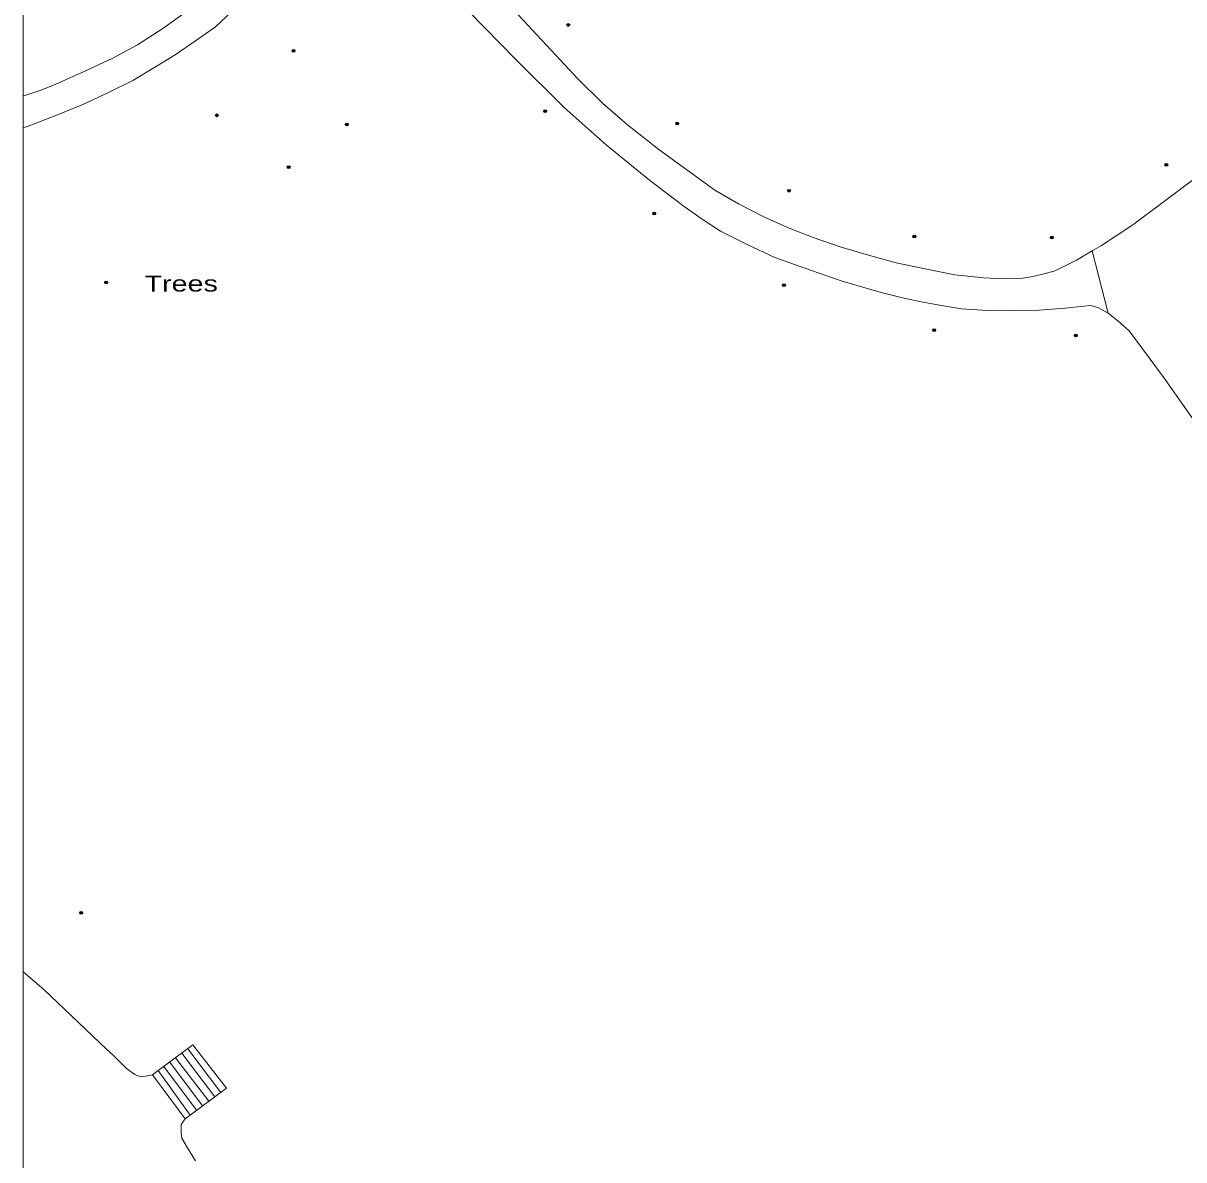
# Model space of a CAD drawing. Extents: x 528790 to 529292, y 179350 to 179856.
# Drawn here: x 528790.2 to 528918, y 179559 to 179684.2 of the extents above; entities that cross this region are included whole.
import ezdxf

# ---------------------------------------------------------------- set-up
doc = ezdxf.new("R2010")
doc.units = 0
doc.header["$LTSCALE"] = 0.6
doc.header["$PDMODE"] = 32
doc.header["$PDSIZE"] = 0.3
for name, color, linetype, lineweight in [('1', 7, 'Continuous', 13), ('2', 7, 'Continuous', 13), ('7', 7, 'Continuous', 13)]:
    doc.layers.add(name, color=color, linetype=linetype, lineweight=lineweight)
doc.layers.add('3', color=7, linetype='Continuous')
doc.layers.add('5', color=7, linetype='Continuous')

msp = doc.modelspace()

# ---------------------------------------------------------------- linework, layer by layer
at = {"layer": '1'}
for points in [[(528790.22, 179728.634), (528790.22, 179676.205), (528790.4, 179676.25), (528792.1, 179676.8), (528793.8, 179677.5), (528797, 179678.9), (528800, 179680.3), (528802.8, 179681.8), (528805.6, 179683.6), (528810, 179686.8)], [(528892.8, 179656.5), (528889.55, 179657.15), (528886.35, 179657.8), (528883.3, 179658.65), (528880.2, 179659.55), (528877.2, 179660.6), (528874.4, 179661.7), (528871.7, 179662.9), (528869, 179664.3), (528866.4, 179665.8), (528860.2, 179670.3), (528856.75, 179673), (528854, 179675.4), (528851.35, 179678.05), (528846.8, 179682.9), (528841.8, 179688.3)], [(528841.8, 179688.3), (528846.8, 179682.9), (528851.35, 179678.05), (528854, 179675.4), (528856.75, 179673), (528860.2, 179670.3), (528866.4, 179665.8), (528869, 179664.3), (528871.7, 179662.9), (528874.4, 179661.7), (528877.2, 179660.6), (528880.2, 179659.55), (528883.3, 179658.65), (528886.35, 179657.8), (528889.55, 179657.15), (528892.8, 179656.5), (528896, 179656.15), (528898.15, 179656.05), (528900.3, 179656.1), (528901.4, 179656.3), (528902.6, 179656.6), (528903.75, 179656.9), (528904.8, 179657.4), (528906.2, 179658.1), (528907.93, 179659.11)], [(528810, 179686.8), (528805.6, 179683.6), (528802.8, 179681.8), (528800, 179680.3), (528797, 179678.9), (528793.8, 179677.5), (528792.1, 179676.8), (528790.4, 179676.25), (528790.22, 179676.205), (528790.22, 179672.699), (528790.6, 179672.8), (528794, 179674.1), (528796.8, 179675.25), (528799.6, 179676.55), (528802.3, 179677.9), (528804.6, 179679.3), (528806.95, 179680.7), (528809.2, 179682.25), (528811.4, 179683.8), (528813.2, 179685.5)], [(528813.2, 179685.5), (528811.4, 179683.8), (528809.2, 179682.25), (528806.95, 179680.7), (528804.6, 179679.3), (528802.3, 179677.9), (528799.6, 179676.55), (528796.8, 179675.25), (528794, 179674.1), (528790.6, 179672.8), (528790.22, 179672.699), (528790.22, 179579.72)], [(528839.3, 179685.5), (528844.5, 179680.15), (528849.8, 179674.9), (528854.4, 179670.8), (528859.2, 179666.9), (528863, 179664), (528865, 179662.6), (528867, 179661.3), (528870, 179659.8), (528873, 179658.4), (528876.2, 179657.25), (528880.4, 179655.8), (528884.7, 179654.55), (528886.9, 179654), (528889.1, 179653.5), (528891.35, 179653.1), (528893.55, 179652.75), (528896.4, 179652.55), (528899.2, 179652.5), (528902.1, 179652.6), (528904.95, 179652.8), (528907.75, 179653.1), (528908.55, 179652.9), (528909.7, 179652.25), (528907.93, 179659.11), (528906.2, 179658.1), (528904.8, 179657.4), (528903.75, 179656.9), (528902.6, 179656.6), (528901.4, 179656.3), (528900.3, 179656.1), (528898.15, 179656.05), (528896, 179656.15), (528892.8, 179656.5)], [(528915.8, 179645.2), (528912, 179650.3), (528910.75, 179651.4), (528909.7, 179652.25), (528908.55, 179652.9), (528907.75, 179653.1), (528904.95, 179652.8), (528902.1, 179652.6), (528899.2, 179652.5), (528896.4, 179652.55), (528893.55, 179652.75), (528891.35, 179653.1), (528889.1, 179653.5), (528886.9, 179654), (528884.7, 179654.55), (528880.4, 179655.8), (528876.2, 179657.25), (528873, 179658.4), (528870, 179659.8), (528867, 179661.3), (528865, 179662.6), (528863, 179664), (528859.2, 179666.9), (528854.4, 179670.8), (528849.8, 179674.9), (528844.5, 179680.15), (528839.3, 179685.5)], [(528907.93, 179659.11), (528908.95, 179659.7), (528912.4, 179662), (528915.75, 179664.5), (528919, 179666.9), (528928.9, 179674), (528937.2, 179679.75), (528937.7, 179679.9), (528938.2, 179680.25), (528938.6, 179680.6), (528939, 179681), (528939.55, 179681.65), (528939.6, 179682.2), (528939.2, 179682.9), (528938.8, 179683.75), (528938.55, 179684.55)], [(528938.55, 179684.55), (528938.8, 179683.75), (528939.2, 179682.9), (528939.6, 179682.2), (528939.55, 179681.65), (528939, 179681), (528938.6, 179680.6), (528938.2, 179680.25), (528937.7, 179679.9), (528937.2, 179679.75), (528928.9, 179674), (528919, 179666.9), (528915.75, 179664.5), (528912.4, 179662), (528908.95, 179659.7), (528907.93, 179659.11), (528909.7, 179652.25), (528910.75, 179651.4), (528912, 179650.3), (528915.8, 179645.2), (528922.05, 179636.3), (528931.35, 179623.2)], [(528979, 179555.1), (528970.3, 179567.6), (528961.7, 179579.8), (528956.2, 179587.65), (528947.3, 179600.3), (528938.9, 179612.3), (528931.35, 179623.2), (528922.05, 179636.3), (528915.8, 179645.2)], [(528809.2, 179558.9), (528808.3, 179560.3), (528807.7, 179561.4), (528807.6, 179561.9), (528807.6, 179562.9), (528808.05, 179563.5), (528804.45, 179568.35), (528803.3, 179568.15), (528803, 179568.2), (528802.5, 179568.4), (528801.6, 179569.05), (528800.15, 179570.5), (528799.4, 179571.2), (528792.5, 179577.75), (528790.22, 179579.72), (528790.22, 179478.28)], [(528790.22, 179579.72), (528792.5, 179577.75), (528799.4, 179571.2), (528800.15, 179570.5), (528801.6, 179569.05), (528802.5, 179568.4), (528803, 179568.2), (528803.3, 179568.15), (528804.45, 179568.35), (528805.09, 179568.82), (528808.9, 179571.65), (528812.6, 179566.9), (528808.59, 179563.91), (528808.05, 179563.5), (528807.6, 179562.9), (528807.6, 179561.9), (528807.7, 179561.4), (528808.3, 179560.3), (528809.2, 179558.9)]]:
    msp.add_lwpolyline(points, dxfattribs=at)
for points in [[(528808.59, 179563.91), (528812.6, 179566.9), (528808.9, 179571.65), (528805.09, 179568.82)], [(528808.05, 179563.5), (528808.59, 179563.91), (528805.09, 179568.82), (528804.45, 179568.35)]]:
    msp.add_lwpolyline(points, close=True, dxfattribs=at)
at = {"layer": '2'}
for p, q in [((528909.7, 179652.25), (528907.93, 179659.11)), ((528805.09, 179568.82), (528808.9, 179571.65)), ((528811.319, 179565.945), (528807.674, 179570.739)), ((528808.335, 179571.23), (528811.971, 179566.431)), ((528808.9, 179571.65), (528812.6, 179566.9)), ((528809.97, 179564.94), (528806.353, 179569.758)), ((528806.983, 179570.226), (528810.659, 179565.453)), ((528804.45, 179568.35), (528805.09, 179568.82)), ((528804.45, 179568.35), (528808.05, 179563.5)), ((528805.09, 179568.82), (528808.59, 179563.91)), ((528805.7, 179569.27), (528809.319, 179564.454)), ((528812.6, 179566.9), (528808.59, 179563.91)), ((528808.59, 179563.91), (528808.05, 179563.5))]:
    msp.add_line(p, q, dxfattribs=at)
for points in [[(528907.93, 179659.11), (528906.2, 179658.1), (528904.8, 179657.4), (528903.75, 179656.9), (528902.6, 179656.6), (528901.4, 179656.3), (528900.3, 179656.1), (528898.15, 179656.05), (528896, 179656.15), (528892.8, 179656.5), (528889.55, 179657.15), (528886.35, 179657.8), (528883.3, 179658.65), (528880.2, 179659.55), (528877.2, 179660.6), (528874.4, 179661.7), (528871.7, 179662.9), (528869, 179664.3), (528866.4, 179665.8), (528860.2, 179670.3), (528856.75, 179673), (528854, 179675.4), (528851.35, 179678.05), (528846.8, 179682.9), (528841.8, 179688.3)], [(528810, 179686.8), (528805.6, 179683.6), (528802.8, 179681.8), (528800, 179680.3), (528797, 179678.9), (528793.8, 179677.5), (528792.1, 179676.8), (528790.4, 179676.25), (528790.22, 179676.205)], [(528813.2, 179685.5), (528811.4, 179683.8), (528809.2, 179682.25), (528806.95, 179680.7), (528804.6, 179679.3), (528802.3, 179677.9), (528799.6, 179676.55), (528796.8, 179675.25), (528794, 179674.1), (528790.6, 179672.8), (528790.22, 179672.699)], [(528909.7, 179652.25), (528908.55, 179652.9), (528907.75, 179653.1), (528904.95, 179652.8), (528902.1, 179652.6), (528899.2, 179652.5), (528896.4, 179652.55), (528893.55, 179652.75), (528891.35, 179653.1), (528889.1, 179653.5), (528886.9, 179654), (528884.7, 179654.55), (528880.4, 179655.8), (528876.2, 179657.25), (528873, 179658.4), (528870, 179659.8), (528867, 179661.3), (528865, 179662.6), (528863, 179664), (528859.2, 179666.9), (528854.4, 179670.8), (528849.8, 179674.9), (528844.5, 179680.15), (528839.3, 179685.5)], [(528938.55, 179684.55), (528938.8, 179683.75), (528939.2, 179682.9), (528939.6, 179682.2), (528939.55, 179681.65), (528939, 179681), (528938.6, 179680.6), (528938.2, 179680.25), (528937.7, 179679.9), (528937.2, 179679.75), (528928.9, 179674), (528919, 179666.9), (528915.75, 179664.5), (528912.4, 179662), (528908.95, 179659.7), (528907.93, 179659.11)], [(528909.7, 179652.25), (528910.75, 179651.4), (528912, 179650.3), (528915.8, 179645.2), (528922.05, 179636.3), (528931.35, 179623.2), (528938.9, 179612.3), (528947.3, 179600.3), (528956.2, 179587.65), (528961.7, 179579.8), (528970.3, 179567.6), (528979, 179555.1), (528980.41, 179553.09)], [(528790.22, 179579.72), (528792.5, 179577.75), (528799.4, 179571.2), (528800.15, 179570.5), (528801.6, 179569.05), (528802.5, 179568.4), (528803, 179568.2), (528803.3, 179568.15), (528804.45, 179568.35)], [(528808.05, 179563.5), (528807.6, 179562.9), (528807.6, 179561.9), (528807.7, 179561.4), (528808.3, 179560.3), (528809.2, 179558.9)]]:
    msp.add_lwpolyline(points, dxfattribs=at)
at = {"layer": '3'}
for p in [(528850.25, 179684), (528820, 179681.15), (528847.7, 179674.5), (528811.55, 179674.05), (528825.85, 179673.05), (528862.25, 179673.15), (528819.45, 179668.35), (528916.1, 179668.6), (528874.55, 179665.75), (528859.7, 179663.25), (528888.35, 179660.7), (528903.5, 179660.6), (528799.35, 179655.65), (528874, 179655.35), (528890.55, 179650.4), (528906.15, 179649.8), (528796.6, 179586.2)]:
    msp.add_point(p, dxfattribs=at)
at = {"layer": '7'}
msp.add_lwpolyline([(528790.22, 179356.024), (529290.22, 179356.024), (529290.22, 179856.024), (528790.22, 179856.024)], close=True, dxfattribs=at)

# ---------------------------------------------------------------- texts
at = {"layer": '5', "width": 1.35}
msp.add_text('Trees', height=1.75, dxfattribs=at).set_placement((528803.58, 179654.64))

doc.saveas('drawing.dxf')
